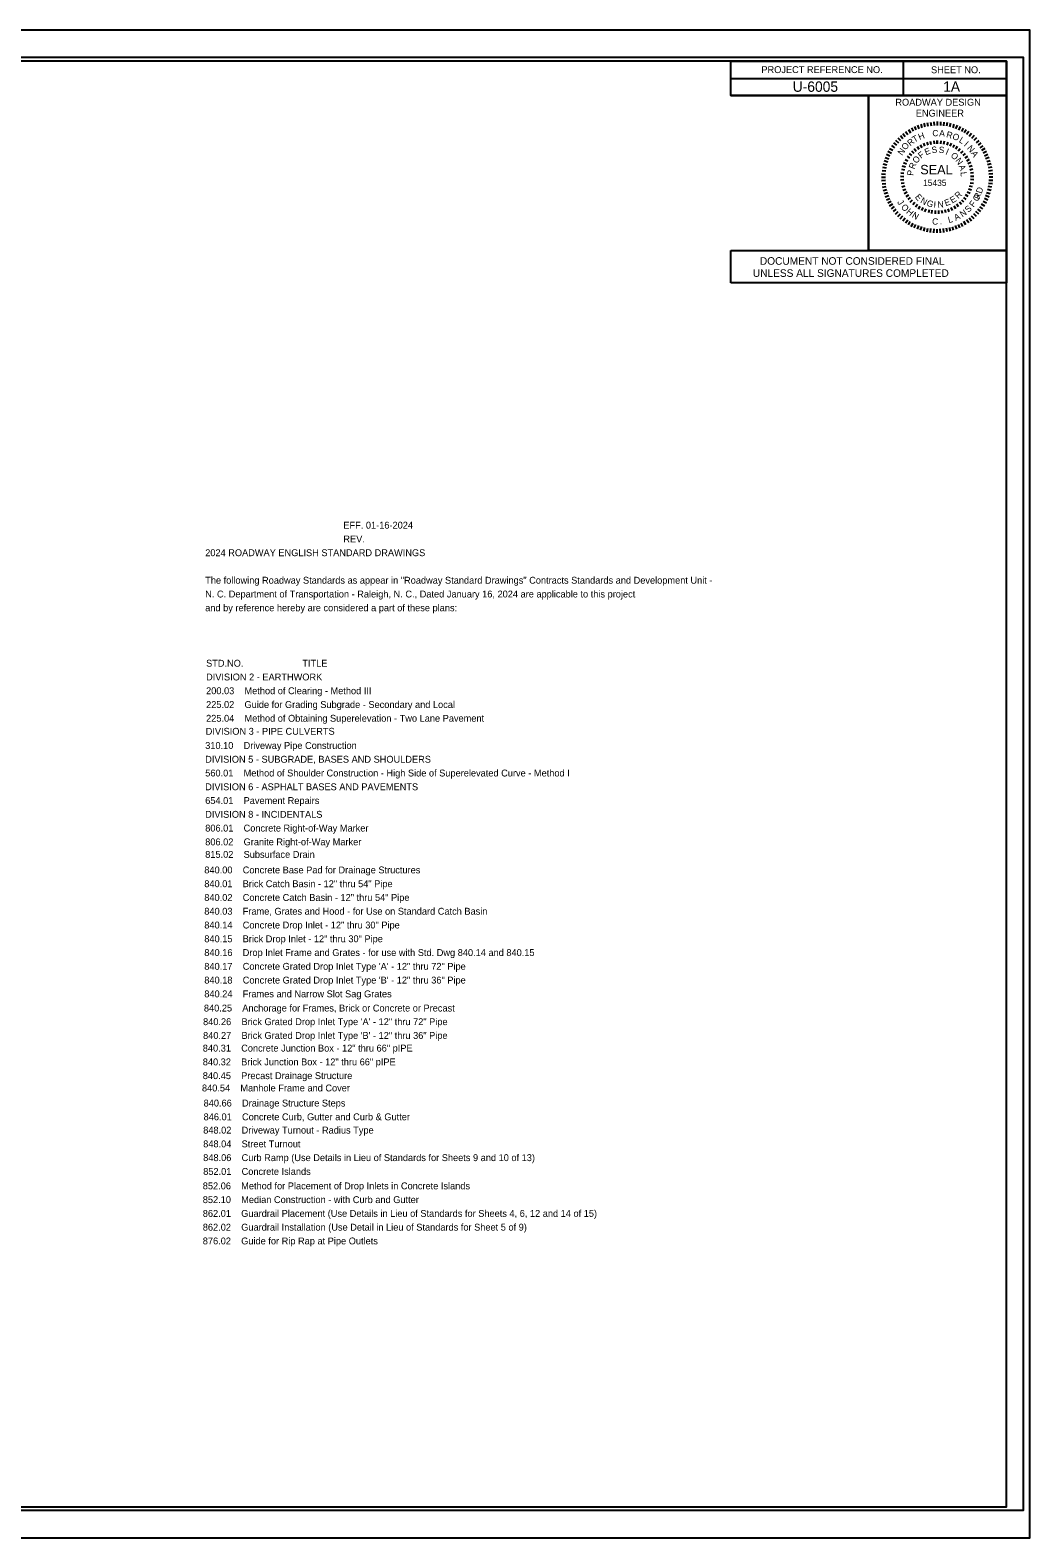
# Model space of a CAD drawing. Extents: x 1773483.6 to 1773517.3, y 886704.6 to 886726.5.
# Drawn here: x 1773502.76 to 1773517.27, y 886704.6 to 886726.5 of the extents above; entities that cross this region are included whole.
import ezdxf

# ---------------------------------------------------------------- set-up
doc = ezdxf.new("R2010")
doc.units = 0
for name, color, linetype in [('Old_Level_21', 7, 'Continuous'), ('Sheet Cutting Line CELL', 7, 'Continuous'), ('Sheet Data Field CELL', 7, 'Continuous'), ('Sheet Plan CELL', 7, 'Continuous'), ('Sheet Plot Border Inside CELL', 7, 'Continuous'), ('Sheet Plot Border Outside CELL', 7, 'Continuous'), ('Sheet Sticker Exception Certification CELL', 7, 'Continuous')]:
    doc.layers.add(name, color=color, linetype=linetype)

msp = doc.modelspace()

# ---------------------------------------------------------------- linework, layer by layer
at = {"layer": 'Old_Level_21'}
for p, q in [((1773515.597, 886725.099), (1773515.619, 886725.049)), ((1773515.642, 886725.118), (1773515.661, 886725.066)), ((1773515.688, 886725.134), (1773515.704, 886725.081)), ((1773515.735, 886725.147), (1773515.748, 886725.093)), ((1773515.783, 886725.157), (1773515.793, 886725.103)), ((1773515.831, 886725.164), (1773515.838, 886725.11)), ((1773515.88, 886725.169), (1773515.883, 886725.114)), ((1773515.928, 886725.17), (1773515.928, 886725.115)), ((1773515.977, 886725.168), (1773515.974, 886725.114)), ((1773516.026, 886725.164), (1773516.019, 886725.109)), ((1773516.074, 886725.157), (1773516.064, 886725.103)), ((1773516.121, 886725.146), (1773516.108, 886725.093)), ((1773516.169, 886725.133), (1773516.152, 886725.081)), ((1773516.215, 886725.117), (1773516.195, 886725.066)), ((1773516.26, 886725.098), (1773516.237, 886725.048)), ((1773515.324, 886724.899), (1773515.365, 886724.862)), ((1773515.357, 886724.934), (1773515.396, 886724.895)), ((1773515.393, 886724.968), (1773515.429, 886724.926)), ((1773515.43, 886724.999), (1773515.464, 886724.956)), ((1773515.469, 886725.028), (1773515.501, 886724.982)), ((1773515.51, 886725.054), (1773515.539, 886725.007)), ((1773515.553, 886725.078), (1773515.579, 886725.029)), ((1773515.776, 886724.873), (1773515.789, 886724.829)), ((1773515.826, 886724.885), (1773515.834, 886724.84)), ((1773515.877, 886724.892), (1773515.881, 886724.847)), ((1773515.928, 886724.895), (1773515.928, 886724.849)), ((1773515.928, 886724.849), (1773515.928, 886724.895)), ((1773515.979, 886724.892), (1773515.975, 886724.847)), ((1773516.03, 886724.885), (1773516.021, 886724.84)), ((1773516.08, 886724.872), (1773516.067, 886724.828)), ((1773516.303, 886725.077), (1773516.278, 886725.028)), ((1773516.346, 886725.053), (1773516.317, 886725.006)), ((1773516.387, 886725.026), (1773516.355, 886724.981)), ((1773516.426, 886724.998), (1773516.392, 886724.954)), ((1773516.463, 886724.966), (1773516.427, 886724.925)), ((1773516.499, 886724.933), (1773516.46, 886724.894)), ((1773516.532, 886724.897), (1773516.491, 886724.861)), ((1773515.173, 886724.65), (1773515.224, 886724.63)), ((1773515.191, 886724.695), (1773515.242, 886724.672)), ((1773515.213, 886724.739), (1773515.262, 886724.713)), ((1773515.237, 886724.781), (1773515.284, 886724.753)), ((1773515.263, 886724.822), (1773515.309, 886724.791)), ((1773515.292, 886724.861), (1773515.336, 886724.827)), ((1773515.49, 886724.666), (1773515.527, 886724.639)), ((1773515.521, 886724.706), (1773515.556, 886724.677)), ((1773515.556, 886724.744), (1773515.588, 886724.711)), ((1773515.595, 886724.778), (1773515.623, 886724.742)), ((1773515.636, 886724.808), (1773515.661, 886724.77)), ((1773515.681, 886724.834), (1773515.702, 886724.794)), ((1773515.727, 886724.856), (1773515.744, 886724.813)), ((1773516.129, 886724.855), (1773516.111, 886724.813)), ((1773516.175, 886724.833), (1773516.154, 886724.793)), ((1773516.219, 886724.807), (1773516.194, 886724.769)), ((1773516.261, 886724.777), (1773516.232, 886724.741)), ((1773516.299, 886724.743), (1773516.267, 886724.71)), ((1773516.334, 886724.705), (1773516.299, 886724.676)), ((1773516.366, 886724.664), (1773516.328, 886724.638)), ((1773516.563, 886724.86), (1773516.52, 886724.826)), ((1773516.592, 886724.82), (1773516.547, 886724.789)), ((1773516.619, 886724.779), (1773516.572, 886724.751)), ((1773516.643, 886724.737), (1773516.594, 886724.711)), ((1773516.664, 886724.693), (1773516.614, 886724.67)), ((1773515.126, 886724.461), (1773515.18, 886724.454)), ((1773515.133, 886724.509), (1773515.187, 886724.499)), ((1773515.144, 886724.557), (1773515.197, 886724.544)), ((1773515.157, 886724.604), (1773515.209, 886724.588)), ((1773515.408, 886724.478), (1773515.453, 886724.468)), ((1773515.421, 886724.528), (1773515.465, 886724.514)), ((1773515.44, 886724.576), (1773515.482, 886724.557)), ((1773515.463, 886724.622), (1773515.503, 886724.6)), ((1773516.393, 886724.621), (1773516.353, 886724.598)), ((1773516.415, 886724.574), (1773516.373, 886724.556)), ((1773516.433, 886724.526), (1773516.39, 886724.512)), ((1773516.447, 886724.477), (1773516.402, 886724.467)), ((1773516.683, 886724.648), (1773516.631, 886724.628)), ((1773516.698, 886724.602), (1773516.646, 886724.586)), ((1773516.711, 886724.555), (1773516.658, 886724.542)), ((1773516.722, 886724.507), (1773516.667, 886724.497)), ((1773516.729, 886724.459), (1773516.674, 886724.452)), ((1773515.12, 886724.364), (1773515.175, 886724.364)), ((1773515.121, 886724.413), (1773515.176, 886724.409)), ((1773515.121, 886724.315), (1773515.176, 886724.318)), ((1773515.126, 886724.266), (1773515.18, 886724.273)), ((1773515.133, 886724.218), (1773515.187, 886724.228)), ((1773515.395, 886724.376), (1773515.441, 886724.375)), ((1773515.396, 886724.325), (1773515.442, 886724.328)), ((1773515.399, 886724.428), (1773515.445, 886724.422)), ((1773515.403, 886724.274), (1773515.448, 886724.281)), ((1773515.414, 886724.224), (1773515.458, 886724.236)), ((1773516.44, 886724.222), (1773516.396, 886724.234)), ((1773516.407, 886724.282), (1773516.452, 886724.274)), ((1773516.456, 886724.426), (1773516.41, 886724.421)), ((1773516.458, 886724.323), (1773516.412, 886724.327)), ((1773516.459, 886724.375), (1773516.413, 886724.374)), ((1773516.721, 886724.216), (1773516.667, 886724.226)), ((1773516.728, 886724.264), (1773516.674, 886724.271)), ((1773516.733, 886724.41), (1773516.678, 886724.407)), ((1773516.733, 886724.313), (1773516.678, 886724.316)), ((1773516.735, 886724.362), (1773516.68, 886724.362)), ((1773515.143, 886724.171), (1773515.196, 886724.184)), ((1773515.156, 886724.124), (1773515.209, 886724.14)), ((1773515.172, 886724.077), (1773515.223, 886724.097)), ((1773515.191, 886724.032), (1773515.241, 886724.055)), ((1773515.212, 886723.988), (1773515.261, 886724.014)), ((1773515.429, 886724.175), (1773515.472, 886724.191)), ((1773515.45, 886724.128), (1773515.491, 886724.148)), ((1773515.475, 886724.083), (1773515.514, 886724.107)), ((1773515.504, 886724.04), (1773515.54, 886724.068)), ((1773515.537, 886724.001), (1773515.571, 886724.032)), ((1773515.574, 886723.965), (1773515.604, 886723.999)), ((1773516.28, 886723.964), (1773516.249, 886723.998)), ((1773516.316, 886724), (1773516.283, 886724.031)), ((1773516.35, 886724.039), (1773516.313, 886724.067)), ((1773516.379, 886724.081), (1773516.34, 886724.105)), ((1773516.404, 886724.126), (1773516.363, 886724.147)), ((1773516.424, 886724.173), (1773516.382, 886724.19)), ((1773516.642, 886723.986), (1773516.593, 886724.012)), ((1773516.663, 886724.03), (1773516.613, 886724.053)), ((1773516.682, 886724.075), (1773516.63, 886724.095)), ((1773516.698, 886724.121), (1773516.645, 886724.138)), ((1773516.711, 886724.168), (1773516.657, 886724.182)), ((1773515.236, 886723.946), (1773515.283, 886723.974)), ((1773515.262, 886723.905), (1773515.307, 886723.936)), ((1773515.291, 886723.866), (1773515.334, 886723.9)), ((1773515.322, 886723.828), (1773515.363, 886723.865)), ((1773515.356, 886723.793), (1773515.394, 886723.831)), ((1773515.391, 886723.759), (1773515.428, 886723.8)), ((1773515.614, 886723.933), (1773515.641, 886723.97)), ((1773515.657, 886723.904), (1773515.68, 886723.944)), ((1773515.702, 886723.88), (1773515.722, 886723.922)), ((1773515.75, 886723.861), (1773515.765, 886723.904)), ((1773515.81, 886723.891), (1773515.799, 886723.846)), ((1773515.85, 886723.836), (1773515.856, 886723.882)), ((1773515.901, 886723.831), (1773515.903, 886723.877)), ((1773515.952, 886723.831), (1773515.95, 886723.877)), ((1773516.003, 886723.836), (1773515.997, 886723.881)), ((1773516.054, 886723.846), (1773516.043, 886723.89)), ((1773516.103, 886723.86), (1773516.088, 886723.904)), ((1773516.151, 886723.88), (1773516.131, 886723.921)), ((1773516.196, 886723.904), (1773516.173, 886723.943)), ((1773516.239, 886723.932), (1773516.212, 886723.969)), ((1773516.462, 886723.758), (1773516.425, 886723.799)), ((1773516.497, 886723.791), (1773516.458, 886723.83)), ((1773516.531, 886723.826), (1773516.49, 886723.863)), ((1773516.562, 886723.864), (1773516.519, 886723.898)), ((1773516.591, 886723.903), (1773516.546, 886723.934)), ((1773516.618, 886723.944), (1773516.571, 886723.973)), ((1773515.428, 886723.728), (1773515.462, 886723.771)), ((1773515.468, 886723.699), (1773515.499, 886723.744)), ((1773515.509, 886723.672), (1773515.537, 886723.719)), ((1773515.551, 886723.648), (1773515.577, 886723.697)), ((1773515.595, 886723.627), (1773515.617, 886723.677)), ((1773515.64, 886723.608), (1773515.659, 886723.66)), ((1773515.686, 886723.592), (1773515.702, 886723.645)), ((1773515.733, 886723.579), (1773515.746, 886723.632)), ((1773515.781, 886723.569), (1773515.791, 886723.623)), ((1773515.829, 886723.561), (1773515.835, 886723.616)), ((1773515.877, 886723.557), (1773515.881, 886723.612)), ((1773515.926, 886723.555), (1773515.926, 886723.61)), ((1773515.975, 886723.557), (1773515.972, 886723.612)), ((1773516.023, 886723.561), (1773516.017, 886723.616)), ((1773516.072, 886723.568), (1773516.062, 886723.622)), ((1773516.119, 886723.578), (1773516.106, 886723.632)), ((1773516.166, 886723.591), (1773516.15, 886723.644)), ((1773516.212, 886723.607), (1773516.193, 886723.659)), ((1773516.257, 886723.626), (1773516.235, 886723.676)), ((1773516.301, 886723.647), (1773516.276, 886723.696)), ((1773516.344, 886723.671), (1773516.315, 886723.718)), ((1773516.385, 886723.698), (1773516.354, 886723.743)), ((1773516.424, 886723.726), (1773516.39, 886723.77))]:
    msp.add_line(p, q, dxfattribs=at)
at = {"layer": 'Sheet Cutting Line CELL'}
for p, q in [((1773517.272, 886726.499), (1773483.602, 886726.499)), ((1773483.602, 886704.599), (1773517.272, 886704.599))]:
    msp.add_line(p, q, dxfattribs=at)
at = {"layer": 'Sheet Plan CELL'}
for p, q in [((1773515.432, 886726.048), (1773515.432, 886725.548)), ((1773512.931, 886725.798), (1773516.932, 886725.798)), ((1773512.931, 886725.548), (1773516.932, 886725.548)), ((1773512.931, 886725.548), (1773516.932, 886725.548)), ((1773514.932, 886725.548), (1773514.932, 886723.299))]:
    msp.add_line(p, q, dxfattribs=at)
for points in [[(1773516.932, 886726.049), (1773486.932, 886726.049), (1773486.932, 886705.049), (1773516.932, 886705.049)], [(1773512.931, 886726.049), (1773516.932, 886726.049), (1773516.932, 886725.548), (1773512.931, 886725.548)], [(1773514.932, 886725.548), (1773516.932, 886725.548), (1773516.932, 886723.298), (1773514.932, 886723.298)]]:
    msp.add_lwpolyline(points, close=True, dxfattribs=at)
at = {"layer": 'Sheet Plot Border Inside CELL'}
msp.add_lwpolyline([(1773483.862, 886704.999), (1773517.182, 886704.999), (1773517.182, 886726.099), (1773483.862, 886726.099)], close=True, dxfattribs=at)
at = {"layer": 'Sheet Plot Border Outside CELL'}
msp.add_lwpolyline([(1773483.602, 886704.599), (1773517.272, 886704.599), (1773517.272, 886726.499), (1773483.602, 886726.499)], close=True, dxfattribs=at)
at = {"layer": 'Sheet Sticker Exception Certification CELL'}
for p, q in [((1773512.931, 886722.828), (1773512.931, 886723.298)), ((1773512.931, 886723.298), (1773516.932, 886723.298)), ((1773516.932, 886723.298), (1773516.932, 886722.828)), ((1773516.932, 886722.828), (1773512.931, 886722.828))]:
    msp.add_line(p, q, dxfattribs=at)

# ---------------------------------------------------------------- texts
at = {"layer": 'Old_Level_21'}
for s, height, rotation, p in [('R', 0.0916, 38.5807, (1773515.537, 886724.81)), ('T', 0.0916, 30.4198, (1773515.598, 886724.862)), ('H', 0.0916, 20.9878, (1773515.672, 886724.901)), ('C', 0.0916, 357.2771, (1773515.855, 886724.96)), ('A', 0.0916, 357.2771, (1773515.955, 886724.958)), ('R', 0.0916, 345.2678, (1773516.052, 886724.944)), ('O', 0.0916, 342.211, (1773516.141, 886724.918)), ('L', 0.0916, 329.0747, (1773516.234, 886724.877)), ('I', 0.0916, 319.4993, (1773516.308, 886724.824)), ('N', 0.0916, 53.5969, (1773515.417, 886724.671)), ('O', 0.0916, 51.6375, (1773515.47, 886724.749)), ('O', 0.0916, 53.457, (1773515.632, 886724.554)), ('F', 0.0916, 38.1608, (1773515.693, 886724.628)), ('E', 0.0916, 22.8645, (1773515.766, 886724.68)), ('S', 0.0916, 7.5683, (1773515.852, 886724.711)), ('S', 0.0916, 352.272, (1773515.944, 886724.719)), ('I', 0.0916, 336.9758, (1773516.041, 886724.699)), ('O', 0.0916, 321.6795, (1773516.115, 886724.663)), ('N', 0.0916, 310.2048, (1773516.354, 886724.78)), ('A', 0.0916, 300.4373, (1773516.414, 886724.713)), ('P', 0.0916, 84.0495, (1773515.581, 886724.381)), ('R', 0.0916, 68.7533, (1773515.595, 886724.472)), ('SEAL', 0.1376, 359.9202, (1773515.681, 886724.404)), ('N', 0.0916, 306.3833, (1773516.185, 886724.602)), ('A', 0.0916, 291.0871, (1773516.236, 886724.526)), ('L', 0.0916, 275.7908, (1773516.265, 886724.436)), ('15435', 0.0916, 359.9202, (1773515.722, 886724.236)), (' RD', 0.0916, 69.5926, (1773516.528, 886724.002)), ('J', 0.0916, 303.8552, (1773515.343, 886723.998)), ('E', 0.0916, 309.9903, (1773515.598, 886724.072)), ('N', 0.0916, 330.8453, (1773515.675, 886723.996)), ('G', 0.0916, 339.6116, (1773515.765, 886723.952)), ('I', 0.0916, 357.7064, (1773515.874, 886723.923)), ('N', 0.0916, 5.336, (1773515.936, 886723.92)), ('E', 0.0916, 20.7281, (1773516.052, 886723.94)), ('E', 0.0916, 30.714, (1773516.146, 886723.979)), ('R', 0.0916, 44.4851, (1773516.234, 886724.043)), ('F', 0.0916, 52.1272, (1773516.455, 886723.919)), ('O ', 0.0916, 60.9198, (1773516.515, 886724.002)), ('O', 0.0916, 311.927, (1773515.395, 886723.924)), ('H', 0.0916, 320.5697, (1773515.47, 886723.847)), ('N', 0.0916, 329.2423, (1773515.551, 886723.785)), ('L', 0.0916, 16.5368, (1773516.098, 886723.695)), ('A', 0.0916, 25.5393, (1773516.197, 886723.728)), ('N', 0.0916, 34.362, (1773516.293, 886723.778)), ('S', 0.0916, 43.2446, (1773516.379, 886723.842)), ('C', 0.0916, 356.0101, (1773515.851, 886723.677)), ('.', 0.0916, 3.7525, (1773515.965, 886723.675))]:
    msp.add_text(s, height=height, rotation=rotation, dxfattribs=at).set_placement(p)
at = {"layer": 'Sheet Data Field CELL'}
for s, p in [('U-6005', (1773513.83, 886725.603)), ('1A ', (1773516.014, 886725.604))]:
    msp.add_text(s, height=0.15, dxfattribs=at).set_placement(p)
at = {"layer": 'Sheet Plan CELL'}
for s, p in [('PROJECT REFERENCE NO.', (1773513.375, 886725.875)), ('SHEET NO.', (1773515.838, 886725.873)), ('ROADWAY DESIGN', (1773515.32, 886725.402)), ('ENGINEER', (1773515.617, 886725.243)), ('                                                      EFF. 01-16-2024', (1773505.3, 886719.258)), ('2024 ROADWAY ENGLISH STANDARD DRAWINGS', (1773505.3, 886718.858)), ('                                                      REV. ', (1773505.3, 886719.058)), ('The following Roadway Standards as appear in "Roadway Standard Drawings" Contracts Standards and Development Unit -', (1773505.3, 886718.458)), ('N. C. Department of Transportation - Raleigh, N. C., Dated January 16, 2024 are applicable to this project', (1773505.3, 886718.258)), ('and by reference hereby are considered a part of these plans:', (1773505.3, 886718.058)), ('STD.NO.                       TITLE', (1773505.313, 886717.253)), ('DIVISION 2 - EARTHWORK', (1773505.313, 886717.053)), ('200.03    Method of Clearing - Method III', (1773505.313, 886716.853)), ('225.02    Guide for Grading Subgrade - Secondary and Local', (1773505.313, 886716.653)), ('225.04    Method of Obtaining Superelevation - Two Lane Pavement', (1773505.313, 886716.453)), ('DIVISION 3 - PIPE CULVERTS', (1773505.307, 886716.264)), ('310.10    Driveway Pipe Construction', (1773505.3, 886716.058)), ('DIVISION 5 - SUBGRADE, BASES AND SHOULDERS', (1773505.3, 886715.858)), ('560.01    Method of Shoulder Construction - High Side of Superelevated Curve - Method I', (1773505.3, 886715.658)), ('DIVISION 6 - ASPHALT BASES AND PAVEMENTS', (1773505.3, 886715.458)), ('654.01    Pavement Repairs', (1773505.3, 886715.258)), ('DIVISION 8 - INCIDENTALS', (1773505.3, 886715.058)), ('806.01    Concrete Right-of-Way Marker', (1773505.3, 886714.858)), ('806.02    Granite Right-of-Way Marker', (1773505.3, 886714.658)), ('815.02    Subsurface Drain', (1773505.3, 886714.476)), ('840.00    Concrete Base Pad for Drainage Structures', (1773505.287, 886714.25)), ('840.01    Brick Catch Basin - 12" thru 54" Pipe', (1773505.287, 886714.05)), ('840.02    Concrete Catch Basin - 12" thru 54" Pipe', (1773505.287, 886713.85)), ('840.03    Frame, Grates and Hood - for Use on Standard Catch Basin', (1773505.287, 886713.65)), ('840.14    Concrete Drop Inlet - 12" thru 30" Pipe', (1773505.287, 886713.45)), ('840.15    Brick Drop Inlet - 12" thru 30" Pipe', (1773505.287, 886713.25)), ('840.16    Drop Inlet Frame and Grates - for use with Std. Dwg 840.14 and 840.15', (1773505.287, 886713.05)), ('840.17    Concrete Grated Drop Inlet Type \'A\' - 12" thru 72" Pipe', (1773505.287, 886712.85)), ('840.18    Concrete Grated Drop Inlet Type \'B\' - 12" thru 36" Pipe', (1773505.287, 886712.65)), ('840.24    Frames and Narrow Slot Sag Grates', (1773505.287, 886712.45)), ('840.25    Anchorage for Frames, Brick or Concrete or Precast', (1773505.281, 886712.244)), ('840.26    Brick Grated Drop Inlet Type \'A\' - 12" thru 72" Pipe', (1773505.269, 886712.046)), ('840.27    Brick Grated Drop Inlet Type \'B\' - 12" thru 36" Pipe', (1773505.269, 886711.846)), ('840.31    Concrete Junction Box - 12" thru 66" pIPE', (1773505.265, 886711.662)), ('840.32    Brick Junction Box - 12" thru 66" pIPE', (1773505.265, 886711.462)), ('840.45    Precast Drainage Structure', (1773505.265, 886711.262)), ('840.54    Manhole Frame and Cover', (1773505.253, 886711.083)), ('840.66    Drainage Structure Steps', (1773505.277, 886710.864)), ('846.01    Concrete Curb, Gutter and Curb & Gutter', (1773505.277, 886710.664)), ('848.02    Driveway Turnout - Radius Type', (1773505.271, 886710.471)), ('848.04    Street Turnout', (1773505.271, 886710.271)), ('848.06    Curb Ramp (Use Details in Lieu of Standards for Sheets 9 and 10 of 13)', (1773505.271, 886710.071)), ('852.01    Concrete Islands', (1773505.271, 886709.871)), ('852.06    Method for Placement of Drop Inlets in Concrete Islands', (1773505.265, 886709.661)), ('852.10    Median Construction - with Curb and Gutter', (1773505.265, 886709.461)), ('862.01    Guardrail Placement (Use Details in Lieu of Standards for Sheets 4, 6, 12 and 14 of 15)', (1773505.265, 886709.261)), ('862.02    Guardrail Installation (Use Detail in Lieu of Standards for Sheet 5 of 9)', (1773505.265, 886709.061)), ('876.02    Guide for Rip Rap at Pipe Outlets', (1773505.265, 886708.861))]:
    msp.add_text(s, height=0.1, dxfattribs=at).set_placement(p)
at = {"layer": 'Sheet Sticker Exception Certification CELL'}
for s, p in [('DOCUMENT NOT CONSIDERED FINAL', (1773513.353, 886723.091)), ('UNLESS ALL SIGNATURES COMPLETED', (1773513.251, 886722.915))]:
    msp.add_text(s, height=0.11, dxfattribs=at).set_placement(p)

doc.saveas('drawing.dxf')
